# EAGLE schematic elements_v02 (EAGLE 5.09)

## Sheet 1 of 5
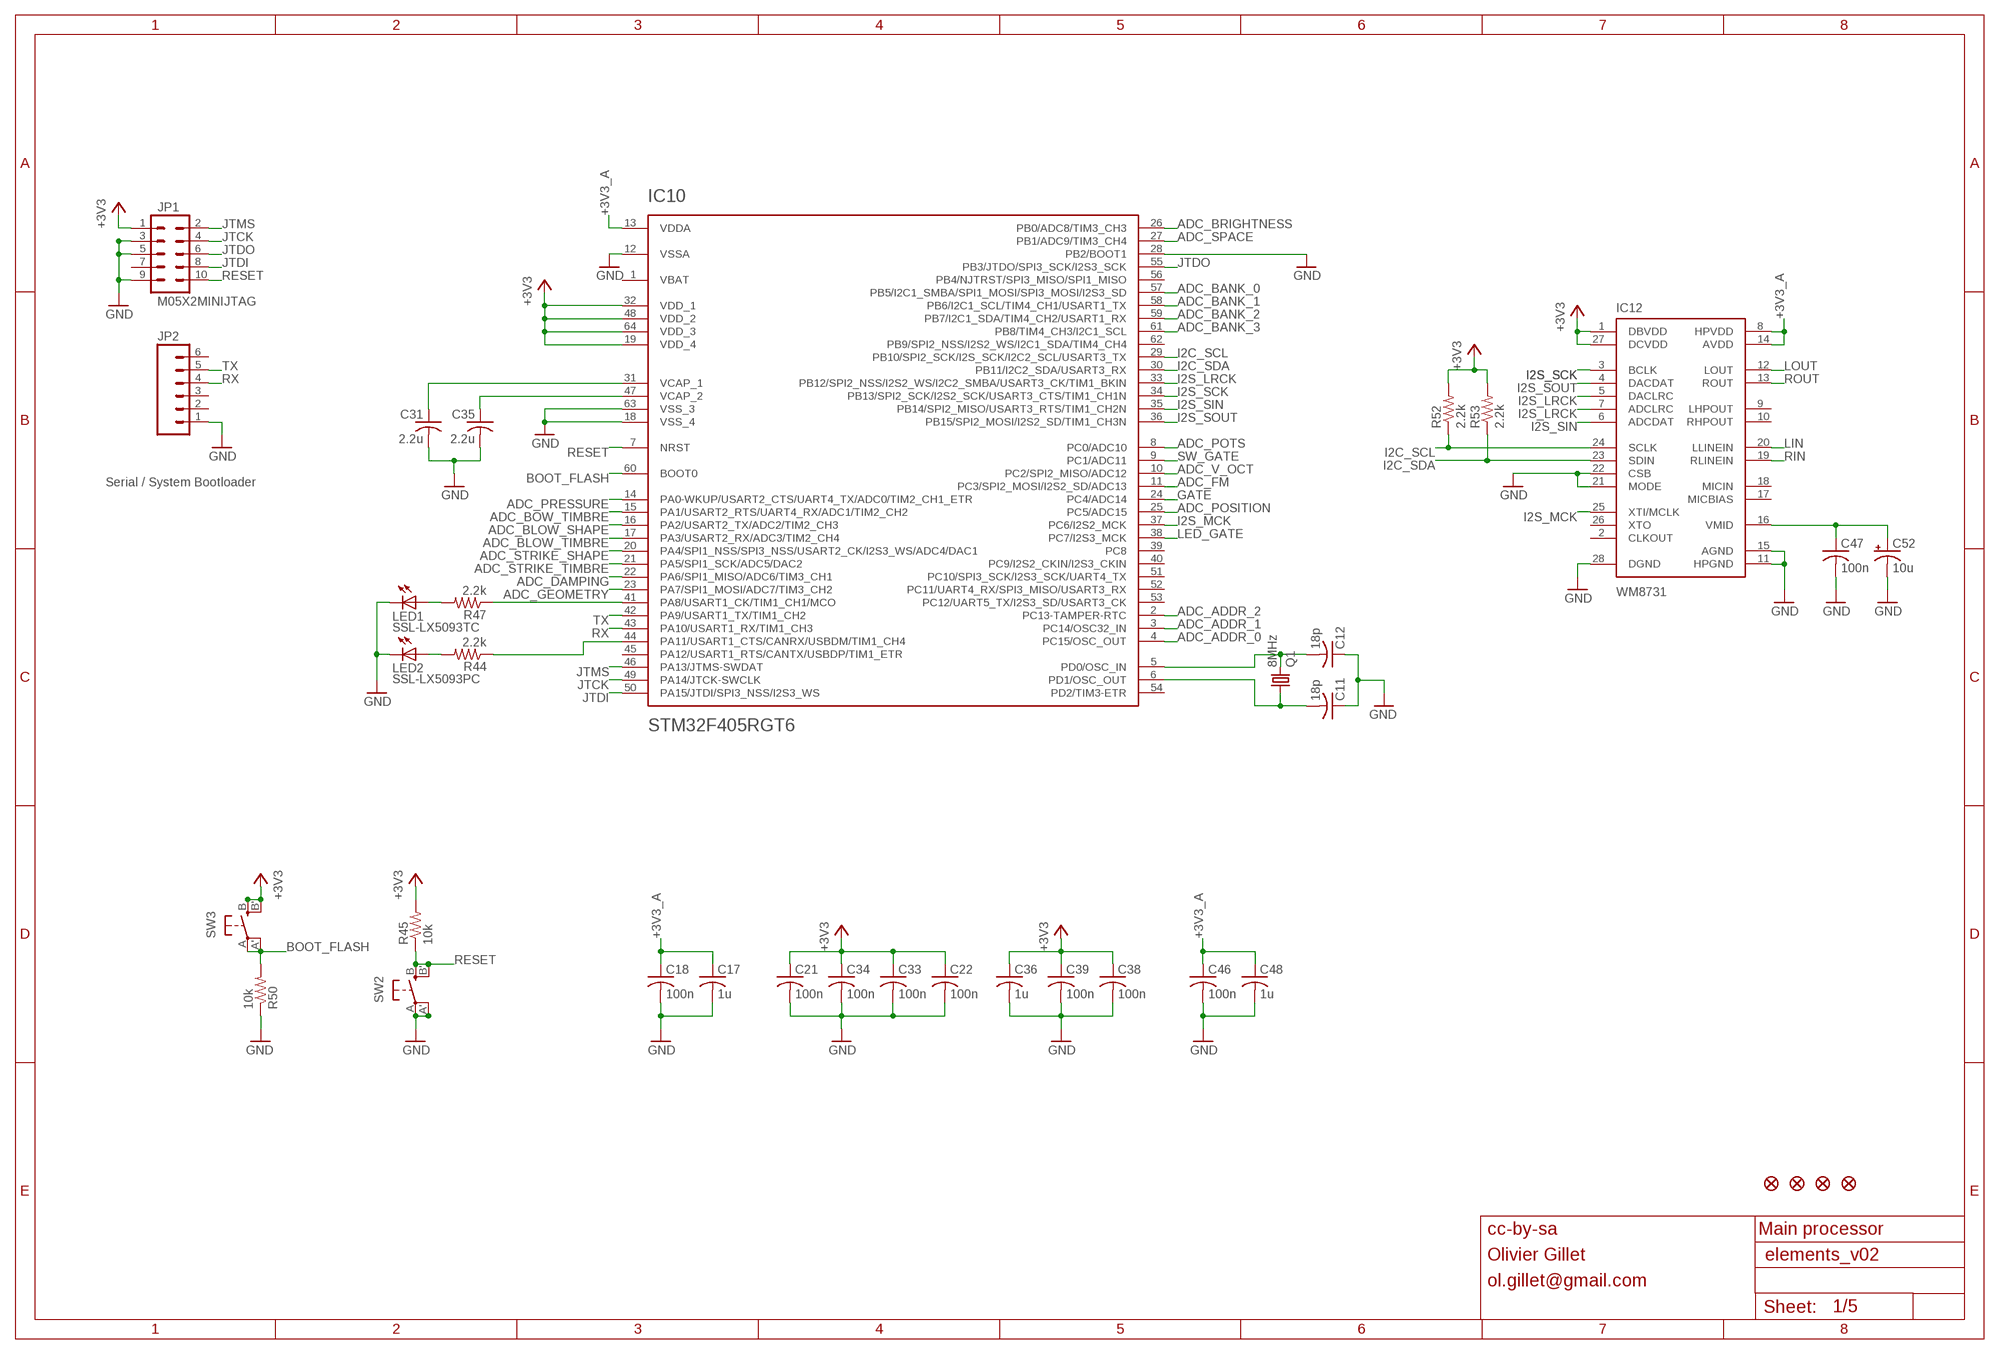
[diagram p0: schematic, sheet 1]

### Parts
C11  18p  C-USC0603  [C0603]
C12  18p  C-USC0603  [C0603]
C17  1u  C-USC0603  [C0603]
C18  100n  C-USC0603  [C0603]
C21  100n  C-USC0603  [C0603]
C22  100n  C-USC0603  [C0603]
C31  2.2u  C-USC0805  [C0805]
C33  100n  C-USC0603  [C0603]
C34  100n  C-USC0603  [C0603]
C35  2.2u  C-USC0805  [C0805]
C36  1u  C-USC0603  [C0603]
C38  100n  C-USC0603  [C0603]
C39  100n  C-USC0603  [C0603]
C46  100n  C-USC0603  [C0603]
C47  100n  C-USC0603  [C0603]
C48  1u  C-USC0603  [C0603]
C52  10u  CPOL-USB  [PANASONIC_B]
F1  FIDUCIAL1X2  [FIDUCIAL-1X2]
F2  FIDUCIAL1X2  [FIDUCIAL-1X2]
F3  FIDUCIAL1X2  [FIDUCIAL-1X2]
F4  FIDUCIAL1X2  [FIDUCIAL-1X2]
IC10  STM32F405RGT6  STM32F20X  [TQFP-10X10-64]
IC12  WM8731  [SSOP28]
JP1  M05X2MINIJTAG  [2X5-1.27]
JP2  M06SIP  [1X06]
LED1  SSL-LX5093TC  LED5MM  [LED5MM]
LED2  SSL-LX5093PC  LED5MM  [LED5MM]
Q1  8MHz  CRYSTALHC49UP  [HC49UP]
R44  2.2k  R-US_R0603  [R0603]
R45  10k  R-US_R0603  [R0603]
R47  2.2k  R-US_R0603  [R0603]
R50  10k  R-US_R0603  [R0603]
R52  2.2k  R-US_R0603  [R0603]
R53  2.2k  R-US_R0603  [R0603]
SW2  EVQQ2  [EVQ-Q2]
SW3  EVQQ2  [EVQ-Q2]

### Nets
+3V3: C21.1 C22.1 C33.1 C34.1 C36.1 C38.1 C39.1 IC10.19(VDD_4) IC10.32(VDD_1) IC10.48(VDD_2) IC10.64(VDD_3) IC12.1(DBVDD) IC12.27(DCVDD) JP1.1 R45.2 R52.2 R53.2 SW3.B'(S1) SW3.B(S) ; also sheet 5
+3V3_A: C17.1 C18.1 C46.1 C48.1 IC10.13(VDDA) IC12.8(HPVDD) IC12.14(AVDD) ; also sheet 3,4,5
ADC_ADDR_0: IC10.4(PC15/OSC_OUT) ; also sheet 4
ADC_ADDR_1: IC10.3(PC14/OSC32_IN) ; also sheet 4
ADC_ADDR_2: IC10.2(PC13-TAMPER-RTC) ; also sheet 4
ADC_BANK_0: IC10.57(PB5/I2C1_SMBA/SPI1_MOSI/SPI3_MOSI/I2S3_SD) ; also sheet 4
ADC_BANK_1: IC10.58(PB6/I2C1_SCL/TIM4_CH1/USART1_TX) ; also sheet 4
ADC_BANK_2: IC10.59(PB7/I2C1_SDA/TIM4_CH2/USART1_RX) ; also sheet 4
ADC_BANK_3: IC10.61(PB8/TIM4_CH3/I2C1_SCL) ; also sheet 4
ADC_BLOW_SHAPE: IC10.16(PA2/USART2_TX/ADC2/TIM2_CH3) ; also sheet 3
ADC_BLOW_TIMBRE: IC10.17(PA3/USART2_RX/ADC3/TIM2_CH4) ; also sheet 3
ADC_BOW_TIMBRE: IC10.15(PA1/USART2_RTS/UART4_RX/ADC1/TIM2_CH2) ; also sheet 3
ADC_BRIGHTNESS: IC10.26(PB0/ADC8/TIM3_CH3) ; also sheet 3
ADC_DAMPING: IC10.22(PA6/SPI1_MISO/ADC6/TIM3_CH1) ; also sheet 3
ADC_FM: IC10.11(PC3/SPI2_MOSI/I2S2_SD/ADC13) ; also sheet 3
ADC_GEOMETRY: IC10.23(PA7/SPI1_MOSI/ADC7/TIM3_CH2) ; also sheet 3
ADC_POSITION: IC10.25(PC5/ADC15) ; also sheet 3
ADC_POTS: IC10.8(PC0/ADC10) ; also sheet 4
ADC_PRESSURE: IC10.14(PA0-WKUP/USART2_CTS/UART4_TX/ADC0/TIM2_CH1_ETR) ; also sheet 3
ADC_SPACE: IC10.27(PB1/ADC9/TIM3_CH4) ; also sheet 3
ADC_STRIKE_SHAPE: IC10.20(PA4/SPI1_NSS/SPI3_NSS/USART2_CK/I2S3_WS/ADC4/DAC1) ; also sheet 3
ADC_STRIKE_TIMBRE: IC10.21(PA5/SPI1_SCK/ADC5/DAC2) ; also sheet 3
ADC_V_OCT: IC10.10(PC2/SPI2_MISO/ADC12) ; also sheet 3
BOOT_FLASH: IC10.60(BOOT0) R50.2 SW3.A'(P1) SW3.A(P)
GATE: IC10.24(PC4/ADC14) ; also sheet 4
GND: C11.1 C12.1 C17.2 C18.2 C21.2 C22.2 C31.2 C33.2 C34.2 C35.2 C36.2 C38.2 C39.2 C46.2 C47.2 C48.2 C52.- IC10.12(VSSA) IC10.18(VSS_4) IC10.28(PB2/BOOT1) IC10.63(VSS_3) IC12.11(HPGND) IC12.15(AGND) IC12.21(MODE) IC12.22(CSB) IC12.28(DGND) JP1.3 JP1.5 JP1.9 JP2.1 LED1.K(C) LED2.K(C) R50.1 SW2.A'(P1) SW2.A(P) ; also sheet 2,3,4,5
I2C_SCL: IC10.29(PB10/SPI2_SCK/I2S_SCK/I2C2_SCL/USART3_TX) IC12.24(SCLK) R52.1
I2C_SDA: IC10.30(PB11/I2C2_SDA/USART3_RX) IC12.23(SDIN) R53.1
I2S_LRCK: IC10.33(PB12/SPI2_NSS/I2S2_WS/I2C2_SMBA/USART3_CK/TIM1_BKIN) IC12.5(DACLRC) IC12.7(ADCLRC)
I2S_MCK: IC10.37(PC6/I2S2_MCK) IC12.25(XTI/MCLK)
I2S_SCK: IC10.34(PB13/SPI2_SCK/I2S2_SCK/USART3_CTS/TIM1_CH1N) IC12.3(BCLK)
I2S_SIN: IC10.35(PB14/SPI2_MISO/USART3_RTS/TIM1_CH2N) IC12.6(ADCDAT)
I2S_SOUT: IC10.36(PB15/SPI2_MOSI/I2S2_SD/TIM1_CH3N) IC12.4(DACDAT)
JTCK: IC10.49(PA14/JTCK-SWCLK) JP1.4
JTDI: IC10.50(PA15/JTDI/SPI3_NSS/I2S3_WS) JP1.8
JTDO: IC10.55(PB3/JTDO/SPI3_SCK/I2S3_SCK) JP1.6
JTMS: IC10.46(PA13/JTMS-SWDAT) JP1.2
LED_GATE: IC10.38(PC7/I2S3_MCK) ; also sheet 4
LIN: IC12.20(LLINEIN) ; also sheet 2
LOUT: IC12.12(LOUT) ; also sheet 2
N$7: C12.2 IC10.5(PD0/OSC_IN) Q1.2
N$8: C11.2 IC10.6(PD1/OSC_OUT) Q1.1
N$13: C35.1 IC10.47(VCAP_2)
N$17: C47.1 C52.+ IC12.16(VMID)
N$19: C31.1 IC10.31(VCAP_1)
N$54: IC10.44(PA11/USART1_CTS/CANRX/USBDM/TIM1_CH4) R44.1
N$59: LED2.A R44.2
N$60: LED1.A R47.2
N$79: IC10.41(PA8/USART1_CK/TIM1_CH1/MCO) R47.1
RESET: IC10.7(NRST) JP1.10 R45.1 SW2.B'(S1) SW2.B(S)
RIN: IC12.19(RLINEIN) ; also sheet 2
ROUT: IC12.13(ROUT) ; also sheet 2
RX: IC10.43(PA10/USART1_RX/TIM1_CH3) JP2.4
SW_GATE: IC10.9(PC1/ADC11) ; also sheet 4
TX: IC10.42(PA9/USART1_TX/TIM1_CH2) JP2.5
Unconnected: IC10.39(PC8) IC10.40(PC9/I2S2_CKIN/I2S3_CKIN) IC10.45(PA12/USART1_RTS/CANTX/USBDP/TIM1_ETR) IC10.51(PC10/SPI3_SCK/I2S3_SCK/UART4_TX) IC10.52(PC11/UART4_RX/SPI3_MISO/USART3_RX) IC10.53(PC12/UART5_TX/I2S3_SD/USART3_CK) IC10.54(PD2/TIM3-ETR) IC10.56(PB4/NJTRST/SPI3_MISO/SPI1_MISO) IC10.62(PB9/SPI2_NSS/I2S2_WS/I2C1_SDA/TIM4_CH4) IC12.2(CLKOUT) IC12.9(LHPOUT) IC12.10(RHPOUT) IC12.17(MICBIAS) IC12.18(MICIN) IC12.26(XTO) JP1.7 JP2.2 JP2.3 JP2.6

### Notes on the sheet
- Serial / System Bootloader
- cc-by-sa | Main processor
- Olivier Gillet
- ol.gillet@gmail.com

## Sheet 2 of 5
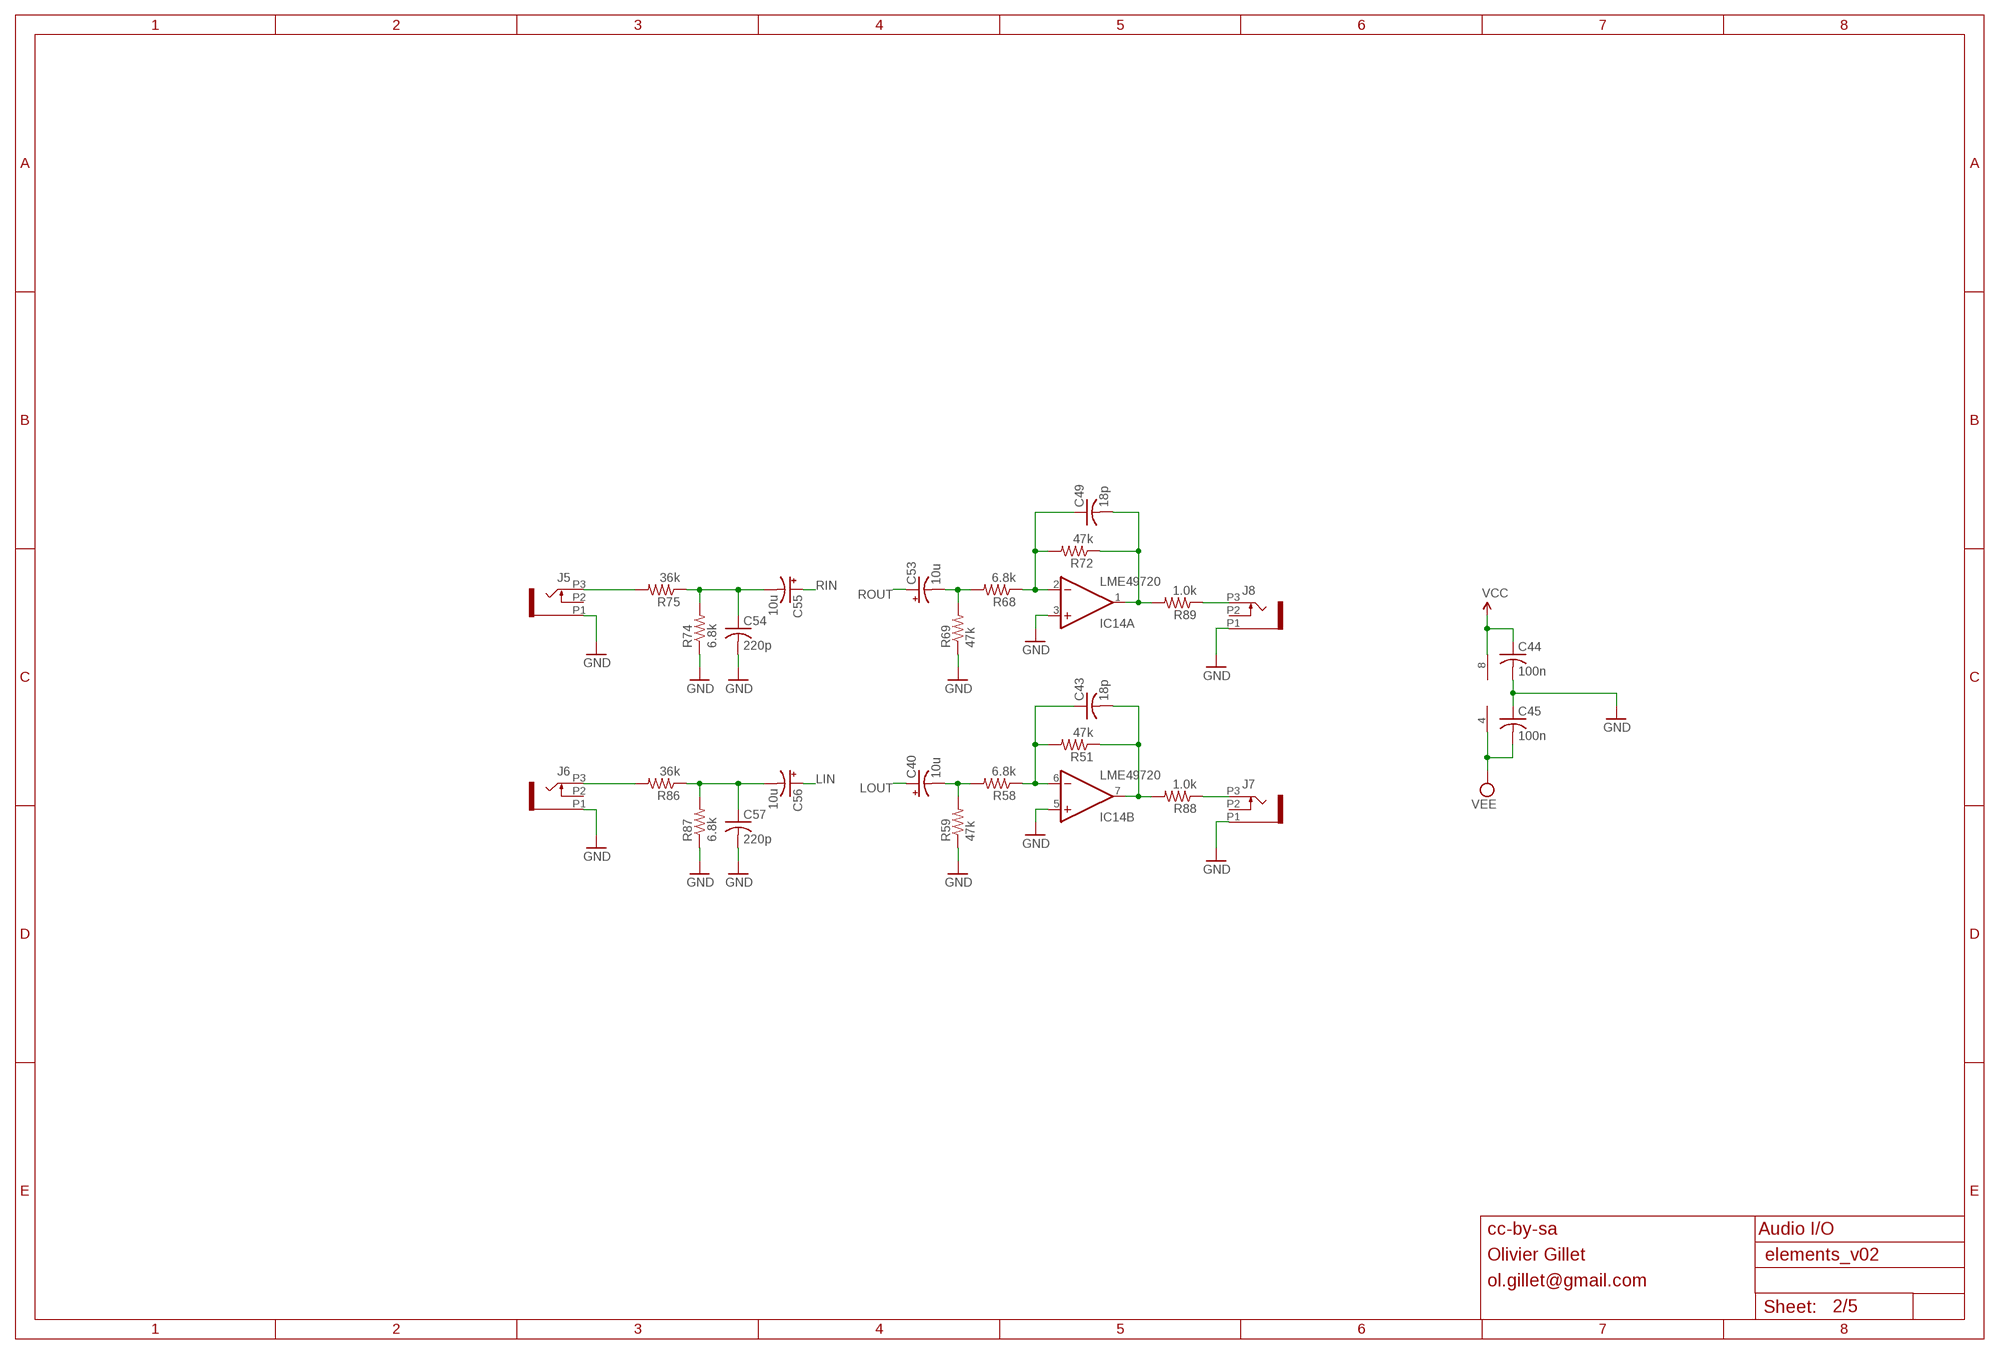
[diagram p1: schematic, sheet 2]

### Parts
C40  10u  CPOL-USB  [PANASONIC_B]
C43  18p  C-USC0603  [C0603]
C44  100n  C-USC0603  [C0603]
C45  100n  C-USC0603  [C0603]
C49  18p  C-USC0603  [C0603]
C53  10u  CPOL-USB  [PANASONIC_B]
C54  220p  C-USC0603  [C0603]
C55  10u  CPOL-USB  [PANASONIC_B]
C56  10u  CPOL-USB  [PANASONIC_B]
C57  220p  C-USC0603  [C0603]
IC14  LME49720  TL072D  [SO08]
J5  PJ301_THONKICONN6  [WQP_PJ_301M6]
J6  PJ301_THONKICONN6  [WQP_PJ_301M6]
J7  PJ301_THONKICONN6  [WQP_PJ_301M6]
J8  PJ301_THONKICONN6  [WQP_PJ_301M6]
R51  47k  R-US_R0603  [R0603]
R58  6.8k  R-US_R0603  [R0603]
R59  47k  R-US_R0603  [R0603]
R68  6.8k  R-US_R0603  [R0603]
R69  47k  R-US_R0603  [R0603]
R72  47k  R-US_R0603  [R0603]
R74  6.8k  R-US_R0603  [R0603]
R75  36k  R-US_R0603  [R0603]
R86  36k  R-US_R0603  [R0603]
R87  6.8k  R-US_R0603  [R0603]
R88  1.0k  R-US_R0603  [R0603]
R89  1.0k  R-US_R0603  [R0603]

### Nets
GND: C44.2 C45.1 C54.2 C57.2 IC14.3(A:+IN) IC14.5(B:+IN) J5.P1 J6.P1 J7.P1 J8.P1 R59.1 R69.1 R74.1 R87.1 ; also sheet 1,3,4,5
LIN: C56.+ ; also sheet 1
LOUT: C40.+ ; also sheet 1
LOUT_JACK: J8.P3 R89.1
N$18: C56.- C57.1 R86.1 R87.2
N$20: J5.P3 R75.2
N$21: J6.P3 R86.2
N$22: C54.1 C55.- R74.2 R75.1
N$23: C40.- R58.2 R59.2
N$25: C43.1 IC14.6(B:-IN) R51.2 R58.1
N$28: C43.2 IC14.7(B:OUT) R51.1 R88.2
N$31: C53.- R68.2 R69.2
N$32: C49.1 IC14.2(A:-IN) R68.1 R72.2
N$33: C49.2 IC14.1(A:OUT) R72.1 R89.2
RIN: C55.+ ; also sheet 1
ROUT: C53.+ ; also sheet 1
ROUT_JACK: J7.P3 R88.1
VCC: C44.1 IC14.8(P:V+) ; also sheet 5
VEE: C45.2 IC14.4(P:V-) ; also sheet 5
Unconnected: J5.P2 J6.P2 J7.P2 J8.P2

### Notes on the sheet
- cc-by-sa | Audio I/O
- Olivier Gillet
- ol.gillet@gmail.com

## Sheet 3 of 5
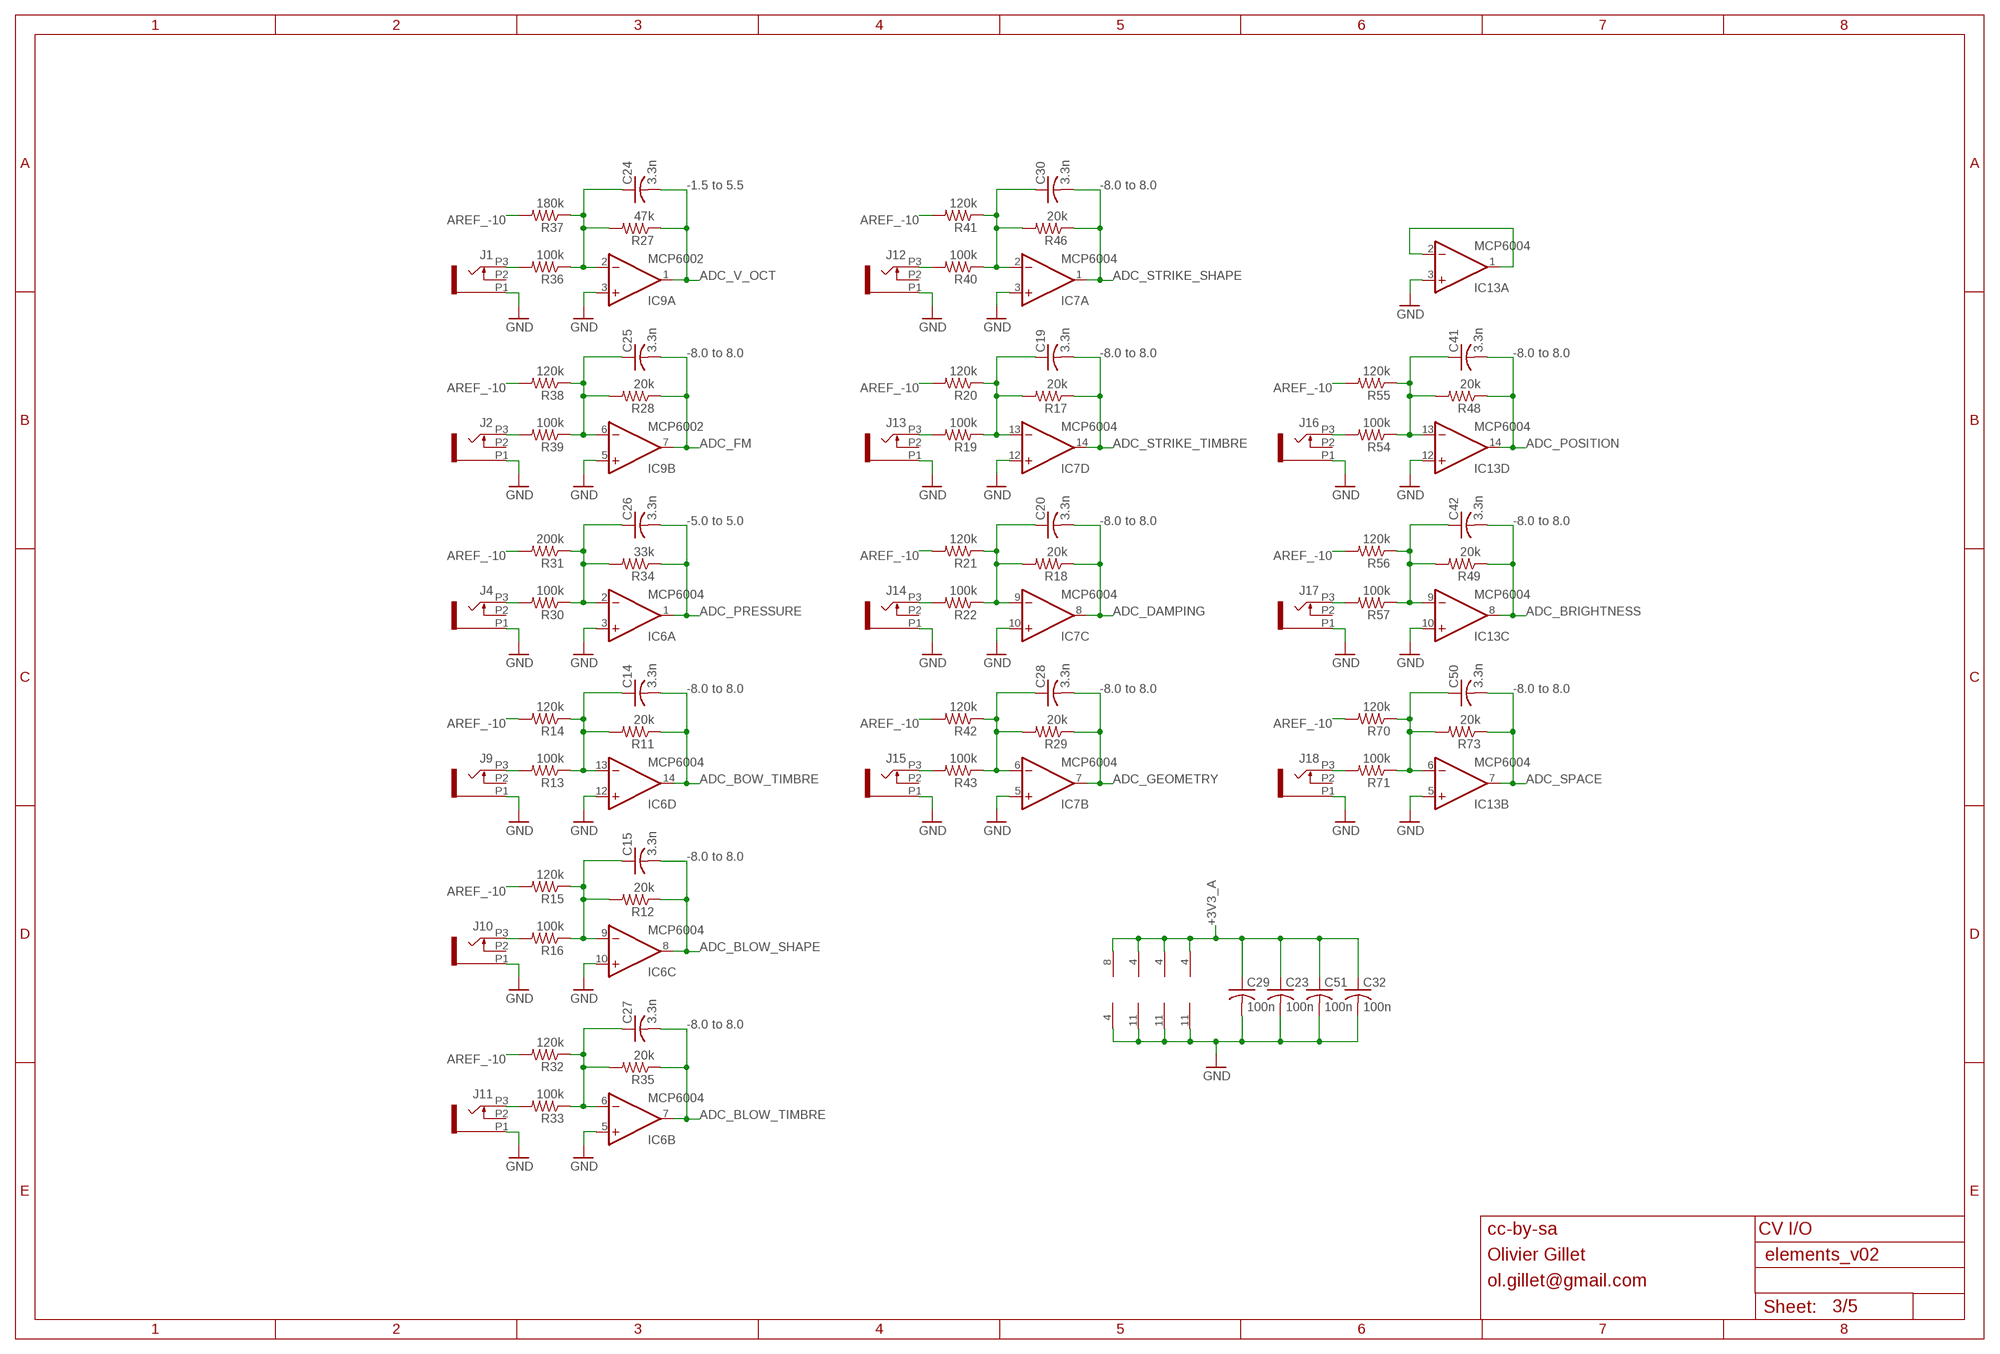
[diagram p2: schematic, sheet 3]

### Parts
C14  3.3n  C-USC0603  [C0603]
C15  3.3n  C-USC0603  [C0603]
C19  3.3n  C-USC0603  [C0603]
C20  3.3n  C-USC0603  [C0603]
C23  100n  C-USC0603  [C0603]
C24  3.3n  C-USC0603  [C0603]
C25  3.3n  C-USC0603  [C0603]
C26  3.3n  C-USC0603  [C0603]
C27  3.3n  C-USC0603  [C0603]
C28  3.3n  C-USC0603  [C0603]
C29  100n  C-USC0603  [C0603]
C30  3.3n  C-USC0603  [C0603]
C32  100n  C-USC0603  [C0603]
C41  3.3n  C-USC0603  [C0603]
C42  3.3n  C-USC0603  [C0603]
C50  3.3n  C-USC0603  [C0603]
C51  100n  C-USC0603  [C0603]
IC6  MCP6004  TL074D  [SO14]
IC7  MCP6004  TL074D  [SO14]
IC9  MCP6002  TL072D  [SO08]
IC13  MCP6004  TL074D  [SO14]
J1  PJ301_THONKICONN6  [WQP_PJ_301M6]
J2  PJ301_THONKICONN6  [WQP_PJ_301M6]
J4  PJ301_THONKICONN6  [WQP_PJ_301M6]
J9  PJ301_THONKICONN6  [WQP_PJ_301M6]
J10  PJ301_THONKICONN6  [WQP_PJ_301M6]
J11  PJ301_THONKICONN6  [WQP_PJ_301M6]
J12  PJ301_THONKICONN6  [WQP_PJ_301M6]
J13  PJ301_THONKICONN6  [WQP_PJ_301M6]
J14  PJ301_THONKICONN6  [WQP_PJ_301M6]
J15  PJ301_THONKICONN6  [WQP_PJ_301M6]
J16  PJ301_THONKICONN6  [WQP_PJ_301M6]
J17  PJ301_THONKICONN6  [WQP_PJ_301M6]
J18  PJ301_THONKICONN6  [WQP_PJ_301M6]
R11  20k  R-US_R0603  [R0603]
R12  20k  R-US_R0603  [R0603]
R13  100k  R-US_R0603  [R0603]
R14  120k  R-US_R0603  [R0603]
R15  120k  R-US_R0603  [R0603]
R16  100k  R-US_R0603  [R0603]
R17  20k  R-US_R0603  [R0603]
R18  20k  R-US_R0603  [R0603]
R19  100k  R-US_R0603  [R0603]
R20  120k  R-US_R0603  [R0603]
R21  120k  R-US_R0603  [R0603]
R22  100k  R-US_R0603  [R0603]
R27  47k  R-US_R0603  [R0603]
R28  20k  R-US_R0603  [R0603]
R29  20k  R-US_R0603  [R0603]
R30  100k  R-US_R0603  [R0603]
R31  200k  R-US_R0603  [R0603]
R32  120k  R-US_R0603  [R0603]
R33  100k  R-US_R0603  [R0603]
R34  33k  R-US_R0603  [R0603]
R35  20k  R-US_R0603  [R0603]
R36  100k  R-US_R0603  [R0603]
R37  180k  R-US_R0603  [R0603]
R38  120k  R-US_R0603  [R0603]
R39  100k  R-US_R0603  [R0603]
R40  100k  R-US_R0603  [R0603]
R41  120k  R-US_R0603  [R0603]
R42  120k  R-US_R0603  [R0603]
R43  100k  R-US_R0603  [R0603]
R46  20k  R-US_R0603  [R0603]
R48  20k  R-US_R0603  [R0603]
R49  20k  R-US_R0603  [R0603]
R54  100k  R-US_R0603  [R0603]
R55  120k  R-US_R0603  [R0603]
R56  120k  R-US_R0603  [R0603]
R57  100k  R-US_R0603  [R0603]
R70  120k  R-US_R0603  [R0603]
R71  100k  R-US_R0603  [R0603]
R73  20k  R-US_R0603  [R0603]

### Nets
+3V3_A: C23.1 C29.1 C32.1 C51.1 IC6.4(P:V+) IC7.4(P:V+) IC9.8(P:V+) IC13.4(P:V+) ; also sheet 1,4,5
ADC_BLOW_SHAPE: C15.2 IC6.8(C:OUT) R12.1 ; also sheet 1
ADC_BLOW_TIMBRE: C27.2 IC6.7(B:OUT) R35.1 ; also sheet 1
ADC_BOW_TIMBRE: C14.2 IC6.14(D:OUT) R11.1 ; also sheet 1
ADC_BRIGHTNESS: C42.2 IC13.8(C:OUT) R49.1 ; also sheet 1
ADC_DAMPING: C20.2 IC7.8(C:OUT) R18.1 ; also sheet 1
ADC_FM: C25.2 IC9.7(B:OUT) R28.1 ; also sheet 1
ADC_GEOMETRY: C28.2 IC7.7(B:OUT) R29.1 ; also sheet 1
ADC_POSITION: C41.2 IC13.14(D:OUT) R48.1 ; also sheet 1
ADC_PRESSURE: C26.2 IC6.1(A:OUT) R34.1 ; also sheet 1
ADC_SPACE: C50.2 IC13.7(B:OUT) R73.1 ; also sheet 1
ADC_STRIKE_SHAPE: C30.2 IC7.1(A:OUT) R46.1 ; also sheet 1
ADC_STRIKE_TIMBRE: C19.2 IC7.14(D:OUT) R17.1 ; also sheet 1
ADC_V_OCT: C24.2 IC9.1(A:OUT) R27.1 ; also sheet 1
AREF_-10: R14.2 R15.2 R20.2 R21.2 R31.2 R32.2 R37.2 R38.2 R41.2 R42.2 R55.2 R56.2 R70.2 ; also sheet 5
GND: C23.2 C29.2 C32.2 C51.2 IC6.3(A:+IN) IC6.5(B:+IN) IC6.10(C:+IN) IC6.11(P:V-) IC6.12(D:+IN) IC7.3(A:+IN) IC7.5(B:+IN) IC7.10(C:+IN) IC7.11(P:V-) IC7.12(D:+IN) IC9.3(A:+IN) IC9.4(P:V-) IC9.5(B:+IN) IC13.3(A:+IN) IC13.5(B:+IN) IC13.10(C:+IN) IC13.11(P:V-) IC13.12(D:+IN) J1.P1 J2.P1 J4.P1 J9.P1 J10.P1 J11.P1 J12.P1 J13.P1 J14.P1 J15.P1 J16.P1 J17.P1 J18.P1 ; also sheet 1,2,4,5
N$1: J10.P3 R16.2
N$2: C15.1 IC6.9(C:-IN) R12.2 R15.1 R16.1
N$3: J13.P3 R19.2
N$4: J9.P3 R13.2
N$5: C14.1 IC6.13(D:-IN) R11.2 R13.1 R14.1
N$6: J2.P3 R39.2
N$9: C19.1 IC7.13(D:-IN) R17.2 R19.1 R20.1
N$10: J1.P3 R36.2
N$11: C24.1 IC9.2(A:-IN) R27.2 R36.1 R37.1
N$12: J14.P3 R22.2
N$14: C20.1 IC7.9(C:-IN) R18.2 R21.1 R22.1
N$15: C25.1 IC9.6(B:-IN) R28.2 R38.1 R39.1
N$16: J12.P3 R40.2
N$24: C30.1 IC7.2(A:-IN) R40.1 R41.1 R46.2
N$26: J11.P3 R33.2
N$27: C27.1 IC6.6(B:-IN) R32.1 R33.1 R35.2
N$29: J17.P3 R57.2
N$30: C42.1 IC13.9(C:-IN) R49.2 R56.1 R57.1
N$34: J18.P3 R71.2
N$35: C50.1 IC13.6(B:-IN) R70.1 R71.1 R73.2
N$36: J15.P3 R43.2
N$37: C28.1 IC7.6(B:-IN) R29.2 R42.1 R43.1
N$39: J16.P3 R54.2
N$40: C41.1 IC13.13(D:-IN) R48.2 R54.1 R55.1
N$41: J4.P3 R30.2
N$42: C26.1 IC6.2(A:-IN) R30.1 R31.1 R34.2
N$44: IC13.1(A:OUT) IC13.2(A:-IN)
Unconnected: J1.P2 J2.P2 J4.P2 J9.P2 J10.P2 J11.P2 J12.P2 J13.P2 J14.P2 J15.P2 J16.P2 J17.P2 J18.P2

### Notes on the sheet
- -1.5 to 5.5 | -8.0 to 8.0
- -8.0 to 8.0 | -8.0 to 8.0 | -8.0 to 8.0
- -5.0 to 5.0 | -8.0 to 8.0 | -8.0 to 8.0
- -8.0 to 8.0 | -8.0 to 8.0 | -8.0 to 8.0
- -8.0 to 8.0
- -8.0 to 8.0
- cc-by-sa | CV I/O
- Olivier Gillet
- ol.gillet@gmail.com

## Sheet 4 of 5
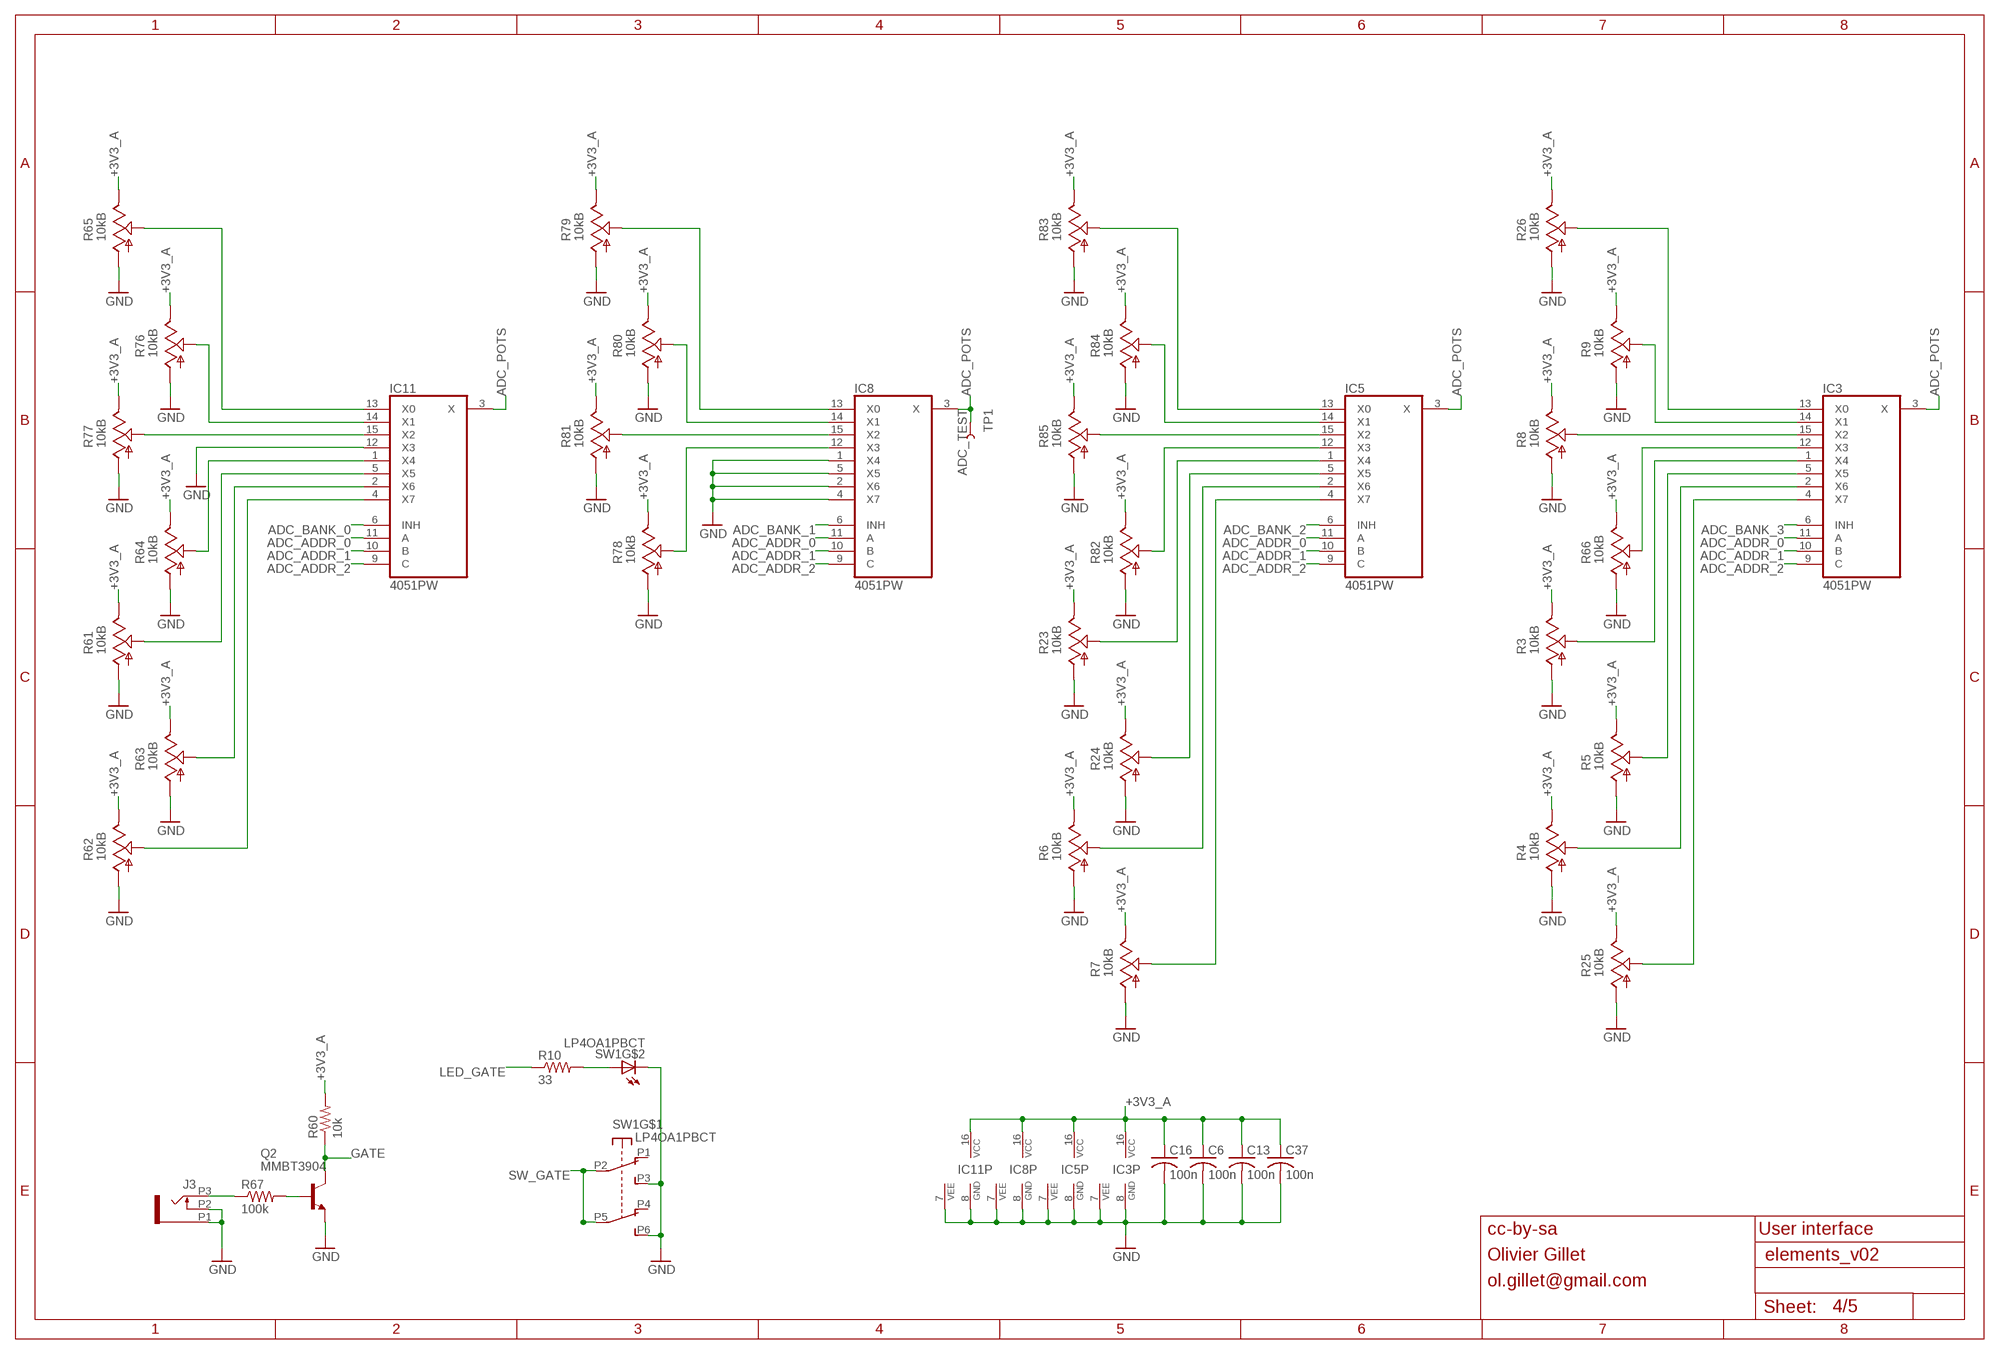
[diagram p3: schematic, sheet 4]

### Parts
C6  100n  C-USC0603  [C0603]
C13  100n  C-USC0603  [C0603]
C16  100n  C-USC0603  [C0603]
C37  100n  C-USC0603  [C0603]
IC3  4051PW  [TSSOP16]
IC5  4051PW  [TSSOP16]
IC8  4051PW  [TSSOP16]
IC11  4051PW  [TSSOP16]
J3  PJ301_THONKICONN6  [WQP_PJ_301M6]
Q2  MMBT3904  MMBT3904LT1-NPN-SOT23-BEC  [SOT23-BEC]
R3  10kB  POT_USVERTICAL_PS  [ALPS_POT_VERTICAL_PS]
R4  10kB  POT_USVERTICAL_PS  [ALPS_POT_VERTICAL_PS]
R5  10kB  POT_USVERTICAL_PS  [ALPS_POT_VERTICAL_PS]
R6  10kB  POT_USVERTICAL_PS  [ALPS_POT_VERTICAL_PS]
R7  10kB  POT_USVERTICAL_PS  [ALPS_POT_VERTICAL_PS]
R8  10kB  POT_USVERTICAL_PS  [ALPS_POT_VERTICAL_PS]
R9  10kB  POT_USVERTICAL_PS  [ALPS_POT_VERTICAL_PS]
R10  33  R-US_R0603  [R0603]
R23  10kB  POT_USVERTICAL_PS  [ALPS_POT_VERTICAL_PS]
R24  10kB  POT_USVERTICAL_PS  [ALPS_POT_VERTICAL_PS]
R25  10kB  POT_USVERTICAL_PS  [ALPS_POT_VERTICAL_PS]
R26  10kB  POT_USVERTICAL_PS  [ALPS_POT_VERTICAL_PS]
R60  10k  R-US_R0603  [R0603]
R61  10kB  POT_USVERTICAL_PS  [ALPS_POT_VERTICAL_PS]
R62  10kB  POT_USVERTICAL_PS  [ALPS_POT_VERTICAL_PS]
R63  10kB  POT_USVERTICAL_PS  [ALPS_POT_VERTICAL_PS]
R64  10kB  POT_USVERTICAL_PS  [ALPS_POT_VERTICAL_PS]
R65  10kB  POT_USVERTICAL_PS  [ALPS_POT_VERTICAL_PS]
R66  10kB  POT_USVERTICAL_PS  [ALPS_POT_VERTICAL_PS]
R67  100k  R-US_R0603  [R0603]
R76  10kB  POT_USVERTICAL  [ALPS_POT_VERTICAL]
R77  10kB  POT_USVERTICAL  [ALPS_POT_VERTICAL]
R78  10kB  POT_USVERTICAL  [ALPS_POT_VERTICAL]
R79  10kB  POT_USVERTICAL  [ALPS_POT_VERTICAL]
R80  10kB  POT_USVERTICAL  [ALPS_POT_VERTICAL]
R81  10kB  POT_USVERTICAL  [ALPS_POT_VERTICAL]
R82  10kB  POT_USVERTICAL  [ALPS_POT_VERTICAL]
R83  10kB  POT_USVERTICAL  [ALPS_POT_VERTICAL]
R84  10kB  POT_USVERTICAL  [ALPS_POT_VERTICAL]
R85  10kB  POT_USVERTICAL  [ALPS_POT_VERTICAL]
SW1  LP4OA1PBCT  [LP4OA1PBCT]
TP1  ADC_TEST  TEST-POINT3  [PAD.03X.03]

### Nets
+3V3_A: C6.1 C13.1 C16.1 C37.1 IC3.16(VCC) IC5.16(VCC) IC8.16(VCC) IC11.16(VCC) R3.P$1(E) R4.P$1(E) R5.P$1(E) R6.P$1(E) R7.P$1(E) R8.P$1(E) R9.P$1(E) R23.P$1(E) R24.P$1(E) R25.P$1(E) R26.P$1(E) R60.2 R61.P$1(E) R62.P$1(E) R63.P$1(E) R64.P$1(E) R65.P$1(E) R66.P$1(E) R76.P$1(E) R77.P$1(E) R78.P$1(E) R79.P$1(E) R80.P$1(E) R81.P$1(E) R82.P$1(E) R83.P$1(E) R84.P$1(E) R85.P$1(E) ; also sheet 1,3,5
ADC_ADDR_0: IC3.11(A) IC5.11(A) IC8.11(A) IC11.11(A) ; also sheet 1
ADC_ADDR_1: IC3.10(B) IC5.10(B) IC8.10(B) IC11.10(B) ; also sheet 1
ADC_ADDR_2: IC3.9(C) IC5.9(C) IC8.9(C) IC11.9(C) ; also sheet 1
ADC_BANK_0: IC11.6(INH) ; also sheet 1
ADC_BANK_1: IC8.6(INH) ; also sheet 1
ADC_BANK_2: IC5.6(INH) ; also sheet 1
ADC_BANK_3: IC3.6(INH) ; also sheet 1
ADC_POTS: IC3.3(X) IC5.3(X) IC8.3(X) IC11.3(X) TP1.P$1 ; also sheet 1
GATE: Q2.C R60.1 ; also sheet 1
GND: C6.2 C13.2 C16.2 C37.2 IC3.7(VEE) IC3.8(GND) IC5.7(VEE) IC5.8(GND) IC8.1(X4) IC8.2(X6) IC8.4(X7) IC8.5(X5) IC8.7(VEE) IC8.8(GND) IC11.7(VEE) IC11.8(GND) IC11.12(X3) J3.P1 J3.P2 Q2.E R3.P$3(A) R4.P$3(A) R5.P$3(A) R6.P$3(A) R7.P$3(A) R8.P$3(A) R9.P$3(A) R23.P$3(A) R24.P$3(A) R25.P$3(A) R26.P$3(A) R61.P$3(A) R62.P$3(A) R63.P$3(A) R64.P$3(A) R65.P$3(A) R66.P$3(A) R76.P$3(A) R77.P$3(A) R78.P$3(A) R79.P$3(A) R80.P$3(A) R81.P$3(A) R82.P$3(A) R83.P$3(A) R84.P$3(A) R85.P$3(A) SW1.L2 SW1.P3(A3) SW1.P6(B3) ; also sheet 1,2,3,5
LED_GATE: R10.1 ; also sheet 1
N$38: R10.2 SW1.L1
N$43: J3.P3 R67.1
N$45: IC11.14(X1) R76.P$2(S)
N$46: IC11.13(X0) R65.P$2(S)
N$47: IC11.15(X2) R77.P$2(S)
N$48: IC11.1(X4) R64.P$2(S)
N$49: IC11.5(X5) R61.P$2(S)
N$50: IC8.14(X1) R80.P$2(S)
N$51: IC8.12(X3) R78.P$2(S)
N$52: IC11.2(X6) R63.P$2(S)
N$53: IC11.4(X7) R62.P$2(S)
N$55: IC3.12(X3) R66.P$2(S)
N$57: IC8.15(X2) R81.P$2(S)
N$58: IC8.13(X0) R79.P$2(S)
N$62: IC3.13(X0) R26.P$2(S)
N$63: IC3.15(X2) R8.P$2(S)
N$65: IC5.12(X3) R82.P$2(S)
N$66: Q2.B R67.2
N$67: IC5.4(X7) R7.P$2(S)
N$68: IC3.14(X1) R9.P$2(S)
N$69: IC5.2(X6) R6.P$2(S)
N$70: IC5.5(X5) R24.P$2(S)
N$71: IC5.1(X4) R23.P$2(S)
N$72: IC3.4(X7) R25.P$2(S)
N$73: IC3.2(X6) R4.P$2(S)
N$74: IC3.1(X4) R3.P$2(S)
N$75: IC3.5(X5) R5.P$2(S)
N$76: IC5.13(X0) R83.P$2(S)
N$77: IC5.14(X1) R84.P$2(S)
N$78: IC5.15(X2) R85.P$2(S)
SW_GATE: SW1.P2(A2) SW1.P5(B2) ; also sheet 1
Unconnected: SW1.P1(A1) SW1.P4(B1)

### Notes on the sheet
- cc-by-sa | User interface
- Olivier Gillet
- ol.gillet@gmail.com

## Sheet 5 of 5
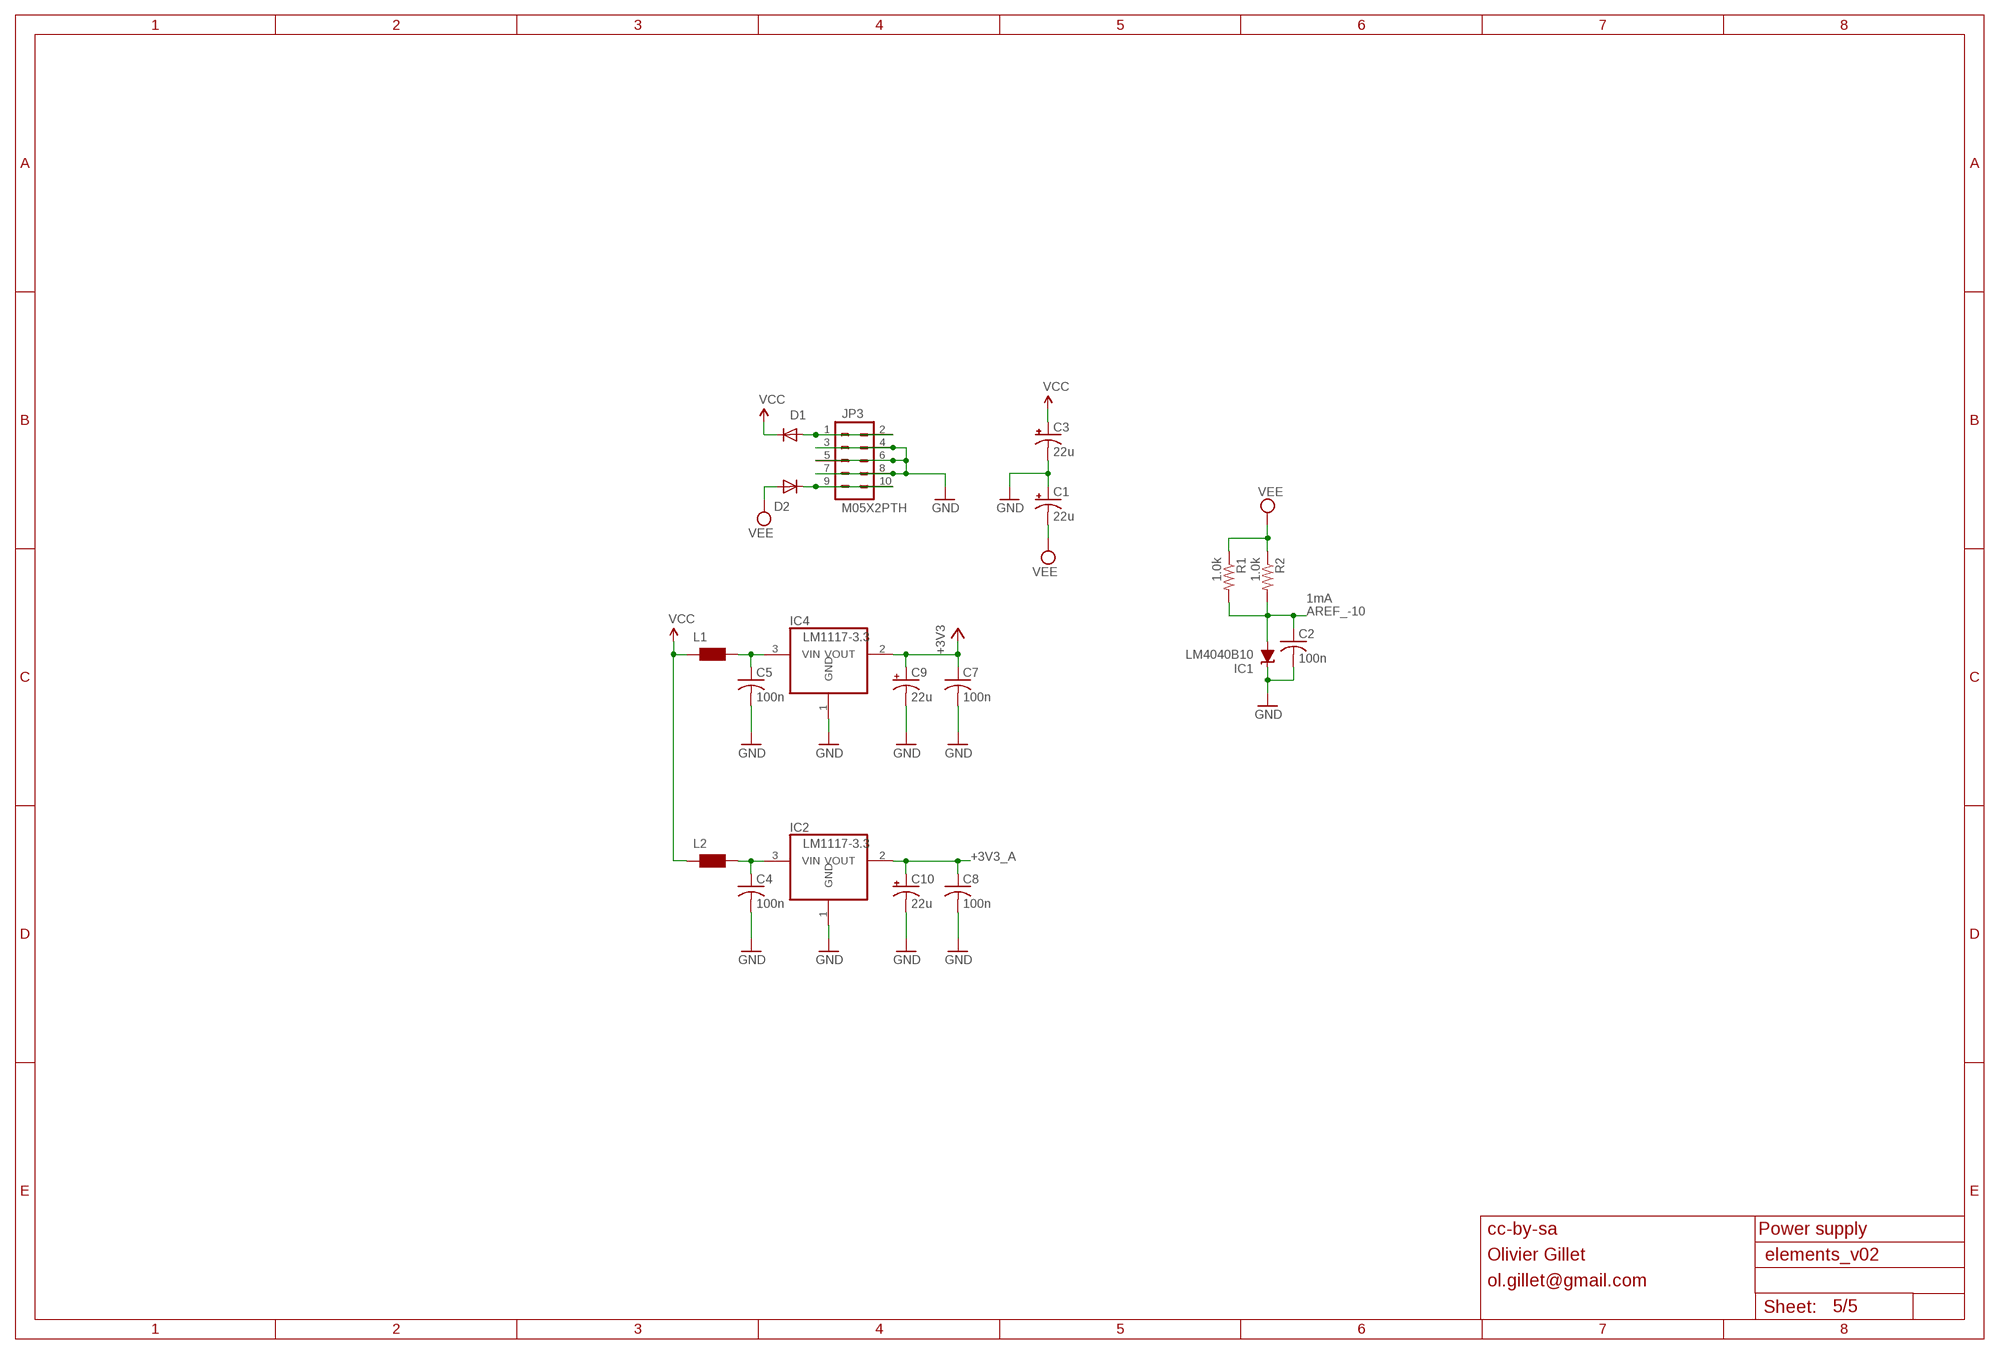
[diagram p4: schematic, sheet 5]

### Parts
C1  22u  CPOL-USC  [PANASONIC_C]
C2  100n  C-USC0603  [C0603]
C3  22u  CPOL-USC  [PANASONIC_C]
C4  100n  C-USC0603  [C0603]
C5  100n  C-USC0603  [C0603]
C7  100n  C-USC0603  [C0603]
C8  100n  C-USC0603  [C0603]
C9  22u  CPOL-USC  [PANASONIC_C]
C10  22u  CPOL-USC  [PANASONIC_C]
D1  1N5819HW  DIODE-SOD123  [SOD123]
D2  1N5819HW  DIODE-SOD123  [SOD123]
IC1  LM4040B10  LM4041B12DBZ  [DBZ_R-PDSO-G3]
IC2  LM1117-3.3  REG1117  [SOT223]
IC4  LM1117-3.3  REG1117  [SOT223]
JP3  M05X2PTH  [AVR_ICSP]
L1  WE-CBF_0603  [0603]
L2  WE-CBF_0603  [0603]
R1  1.0k  R-US_R0603  [R0603]
R2  1.0k  R-US_R0603  [R0603]

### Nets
+3V3: C7.1 C9.+ IC4.2(VOUT) ; also sheet 1
+3V3_A: C8.1 C10.+ IC2.2(VOUT) ; also sheet 1,3,4
AREF_-10: C2.1 IC1.2(A) R1.2 R2.2 ; also sheet 3
GND: C1.+ C2.2 C3.- C4.2 C5.2 C7.2 C8.2 C9.- C10.- IC1.1(C) IC2.1(GND) IC4.1(GND) JP3.3 JP3.4 JP3.5 JP3.6 JP3.7 JP3.8 ; also sheet 1,2,3,4
N$56: D1.A JP3.1 JP3.2
N$61: C5.1 IC4.3(VIN) L1.2
N$64: D2.C JP3.9 JP3.10
N$80: C4.1 IC2.3(VIN) L2.2
VCC: C3.+ D1.C L1.1 L2.1 ; also sheet 2
VEE: C1.- D2.A R1.1 R2.1 ; also sheet 2

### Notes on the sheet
- 1mA
- cc-by-sa | Power supply
- Olivier Gillet
- ol.gillet@gmail.com

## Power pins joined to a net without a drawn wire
VBAT: IC10.1(VBAT)

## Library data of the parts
C1 C3 C9 C10 C40 C52 C53 C55 C56 = rcl:CPOL-US: POLARIZED CAPACITOR, American symbol
C2 C4-C8 C11-C39 C41-C51 C54 C57 = rcl:C-US: CAPACITOR, American symbol
D1 D2 = diode:DIODE-: DIODE
F1-F4 = SparkFun:FIDUCIAL: Fiducial Alignment Points
IC1 = texas:LM4041: PRECISION MICROPOWER SHUNT VOLTAGE REFERENCE
IC2 IC4 = og-vreg:REG1117: 800mA and 1A Low Dropout (LDO) Positive Regulator 1.8V, 2.5V, 2.85V, 3.3V, 5V, and Adj
IC3 IC5 IC8 IC11 = og-ics:4051: 8-channel ANALOG MULTIPLEXER
IC6 IC7 IC13 = gm-ics:TL074: OP AMP
IC9 = gm-ics:TL072: OP AMP
IC10 = og-stm32f2:STM32F20X
IC12 = og-dac:WM8731
IC14 = og-linear:TL072: OP AMP
J1-J18 = og-pj301:PJ301_THONKICONN
JP1 JP3 = og-header:M05X2: Header 5x2 Standard 10-pin dual row 0.1" header. Commonly used with AVR-ISP. Use with Spark Fun Electronics SKU: PRT-00778
JP2 = SparkFun:M06: Header 6 Standard 6-pin 0.1" header. Use with straight break away headers (SKU : PRT-00116), right angle break away headers (PRT-00553), swiss pins (PRT-00743), machine pins (PRT-00117), and female headers (PRT-00115). Molex polarized connector foot print use with SKU : PRT-08094 with associated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
L1 L2 = wuerth-elektronik:WE-CBF: SMD EMI Suppression Ferrite Beads
LED1 LED2 = led:LED: LED
Q1 = crystal:CRYSTAL: CRYSTAL
Q2 = transistor:*-NPN-: NPN Transistror BF959 corrected 2008.03.06
R1 R2 R10-R22 R27-R60 R67-R75 R86-R89 = rcl:R-US_: RESISTOR, American symbol
R3-R9 R23-R26 R61-R66 R76-R85 = og-pots:POT_US
SW1 = og-switch:LP4OA1PBCT
SW2 SW3 = adafruit:EVQQ2: SMT 6mm switch, EVQQ2 series http://www.ladyada.net/library/eagle
TP1 = SparkFun:TEST-POINT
